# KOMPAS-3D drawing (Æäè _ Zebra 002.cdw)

Views: Спереди 1, Спереди, Проекционный вид 2, Проекционный вид 3, Разрез Б-Б, Разрез В-В, Вид по стрелке 8, Разрез Г-Г, Вид 10, Диметрия, Вид 11, Вид 12, Изометрия XYZ
Referenced files in D:\работа\Чертежи\Компенсатор\Пламегаситель Свечка\: Компенсатор.m3d, ТДК _ Zebra 002.cdw
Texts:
  Zebra 002
  ТДК
  Александр
  Лит-Масса-Масштаб
  Материал-Предприятие
  Title Specification
  Body Specification ( left align )
  Body Specificaton ( centered )
  Поз.
  Кол.
  Приме-
  чание
  Таблица спецификации
  Сталь 20 ГОСТ 1050-88
  Чередниченко А.В.
  Zebra 002-
Dimensions and other numbers on the sheet: 9,5; 2; 3; 7; 31,5; 5; 1; 120; 24Х1,5; 24,5; 22,3; 8; 20; 27; 18Х1; 14; 10; 11; 29; 19; 21; 2,5; 4,5; 4; 0; 1:1; 0,1; 21.06.2015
